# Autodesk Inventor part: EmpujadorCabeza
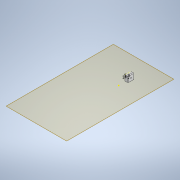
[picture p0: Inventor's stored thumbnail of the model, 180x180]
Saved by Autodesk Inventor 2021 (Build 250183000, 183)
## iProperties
Created: 2021-02
Part Number: EmpujadorCabeza
Material: Genérico
Document SubType Name: Modeling
Designer: ATOUZA
Mass: 27.4687 g
Surface Area: 54.711 cm^2
Volume: 27.4687 cm^3
Density: 1 g/cm^3
Appearance: Valor por defecto
Author: ATOUZA
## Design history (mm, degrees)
node "Plano de trabajo1"
sketch "Boceto1"
  geometry: L1 (0, -16)-(16, -16); L2 (16, -16)-(16, 16); L3 (16, 16)-(0, 16); L4 (0, 16)-(0, -16); L5 (0, -16)-(16, 16); L6 (16, -16)-(0, 16); L7 (0, 16)-(0, 0); L8 (0, 8)-(16, 8); L9 (0, 0)-(0, -16); L10 (0, -8)-(16, -8); C1 r 1.9 at (8, 8); C2 r 1.9 at (8, -8); 2 further points
  constraints: 20 end point, 7 midpoint, 2 centre point, 2 horizontal, 2 parallel, 2 perpendicular, 1 vertical
  dimensions: "d23" = 16 distance of L3.end L2.end; "d24" = 32 distance of L2.end L1.end; "d35" = 3.8 diameter of C1; "d36" = 3.8 diameter of C2
extrude "Extrusión2" new body sketch "Boceto1" distance "d29" = 28.5; taper "d30" = 0 deg
fillet "Empalme4" dims "d37" = 4
sketch "Boceto5"
  geometry: L1 (0, 0)-(0, 28.5) reference; L2 (0, 14.5)-(31.407, 14.5); L3 (0, 28.5)-(32, 28.5) reference; C1 r 2.9 at (16, 14.5); 1 further point
  constraints: 2 end point, 2 point on line, 1 centre point, 1 horizontal
  dimensions: "d38" = 5.8 diameter of C1; "d41" = 14 distance from line of L3 C1.centre
extrude "Extrusión4" cut sketch "Boceto5" extent not by distance; stored distance "d39" = 0; taper "d40" = 0 deg
node "Sólido2"
other parameters: "d3" = 16
